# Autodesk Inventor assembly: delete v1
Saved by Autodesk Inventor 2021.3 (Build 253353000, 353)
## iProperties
Created: 2024-03
Part Number: delete v1
Document SubType Name: Assembly
Designer: AdminForWorker
Title: delete v1 v2
Author: AdminForWorker
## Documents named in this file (5)
- c:\worker\convert-fusion-r01-cosv3\tmp\job-1\209\temp\files\e4f8ace8-0d63-439e-98de-fbbfa7024e54\98c0a37e-888b-4aa6-b77f-46cf52c83d50.iam
- c:\worker\convert-fusion-r01-cosv3\tmp\job-1\209\temp\files\e4f8ace8-0d63-439e-98de-fbbfa7024e54\Copper.ipt
- c:\worker\convert-fusion-r01-cosv3\tmp\job-1\209\temp\files\e4f8ace8-0d63-439e-98de-fbbfa7024e54\Al 5 axis.ipt
- c:\worker\convert-fusion-r01-cosv3\tmp\job-1\209\temp\files\e4f8ace8-0d63-439e-98de-fbbfa7024e54\Al 2.ipt
- c:\worker\convert-fusion-r01-cosv3\tmp\job-1\209\temp\files\e4f8ace8-0d63-439e-98de-fbbfa7024e54\Brass.ipt
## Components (4 placed, 4 different names)
1. Copper:1
2. Al 5 axis:1
3. Al 2:1
4. Brass:1
